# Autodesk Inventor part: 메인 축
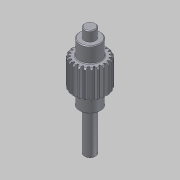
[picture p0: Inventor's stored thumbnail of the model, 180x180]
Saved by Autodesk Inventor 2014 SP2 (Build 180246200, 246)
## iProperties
Created: 2014-07
Part Number: 메인 축
Material: 강
Document SubType Name: Modeling
Designer: KYOUNG IL JANG
Categories: <?xml version="1.0" encoding="UTF-16"?> <MemberInstance><Categories><FamilyTemplate><FamilyTemplateParameter ValueType="xs:double" Id="1" ObjectReferenceKey="da
Density: 1 g/cm^3
Appearance: 강철
CustomPartVersion: 1
Company: 한국ATC센터
Author: KYOUNG IL JANG
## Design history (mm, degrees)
sketch "Sketch1"
  geometry: C1 r 12 at (0, 0)
  constraints: 1 centre point
  dimensions: "d0" = 24 diameter of C1 (= da_da)
extrude "Extrusion1" new body sketch "Sketch1" distance "d1" = 20 (= da_b); taper "d2" = 0 deg
workplane "Work Plane2"
feature "피치 지름" dims "d4" = 10, "d5" = 0
workplane "Work Plane8"
workplane "Work Plane9"
chamfer "모따기1" distance "d49" = 1; stored, may be unused: second distance "d50" = 2, angle "d51" = 45 deg
sketch "스케치3"
  geometry: C1 r 7.5 at (0, 0); 1 further point
  constraints: 1 centre point, 1 coincident
  dimensions: "d52" = 15 diameter of C1
extrude "돌출2" join sketch "스케치3" distance "d53" = 11; taper "d54" = 0 deg
sketch "스케치4"
  geometry: C1 r 4 at (0, 0); 1 further point
  constraints: 1 centre point, 1 coincident
  dimensions: "d55" = 8 diameter of C1
extrude "돌출3" join sketch "스케치4" distance "d56" = 7; taper "d57" = 0 deg
sketch "스케치5"
  geometry: C1 r 7.5 at (0, 0) reference; C2 r 7.5 at (0, 0) reference; 1 further point
extrude "돌출4" join sketch "스케치5" distance "d62" = 11; taper "d63" = 0 deg
sketch "스케치6"
  geometry: C1 r 4 at (0, 0); 1 further point
  constraints: 1 centre point, 1 coincident
  dimensions: "d64" = 8 diameter of C1
extrude "돌출5" join sketch "스케치6" distance "d65" = 30; taper "d66" = 0 deg
chamfer "모따기2" distance "d58" = 0.5; stored, may be unused: second distance "d59" = 2, angle "d60" = 45 deg
fillet "모깎기1" dims "d61" = 0.5
feature "스퍼 기어" dims "da_b" = 20, "da_d" = 22, "da_aw" = 31, "da_da" = 24, "da_df" = 19.5, "da_dw" = 22, angle "da_beta" = 0 deg, "da_lefttooth" = 0, "da_righttooth" = 0
body "Solid1"
sketch "Sketch2"
  geometry: C1 r 12 at (0, 0) reference; C2 r 11 at (0, 0)
  constraints: 1 centre point, 1 coincident
  dimensions: "d3" = 22 diameter of C2 (= da_dw)
body "Srf1"
node "투영된 루프1"
other parameters: "d16" = 31 (= da_aw), "d17" = 0, "d34" = 1.428 (computed from da_z), "d39" = 0, "d41" = 0, "d43" = 31 (= da_aw), "d46" = 31 (= da_aw), "d47" = 0, "d48" = 0
